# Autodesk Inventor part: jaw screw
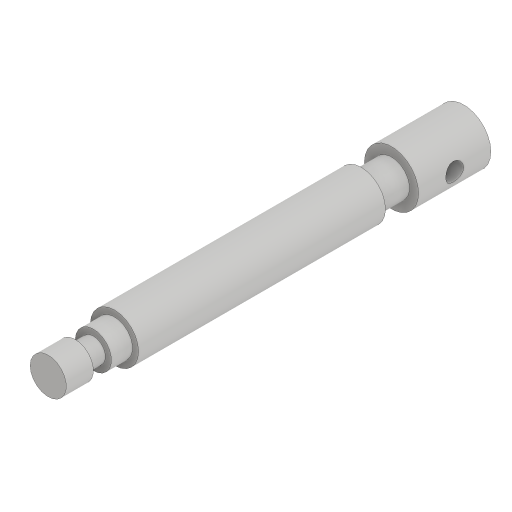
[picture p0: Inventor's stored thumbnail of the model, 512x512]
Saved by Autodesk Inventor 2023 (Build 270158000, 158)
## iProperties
Created: 2016-03
Part Number: jaw screw
Material: Generic
Document SubType Name: Modeling
Designer: Sandeep
Density: 1 g/cm^3
Appearance: Default
Mass: 25.5852 g
Surface Area: 75.8462 cm^2
Volume: 25.5852 cm^3
Author: Sandeep
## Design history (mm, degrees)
sketch "Sketch1"
  geometry: L1 (0, -138)-(-6, -138); L2 (-6, -116)-(-6, -116); L3 (-6, -116)-(-8, -116); L4 (-8, -116)-(-8, -34); L5 (-8, -34)-(-6, -34); L6 (-6, -34)-(-6, -24); L7 (-6, -24)-(-9, -24); L8 (-9, -24)-(-9, 0); L9 (-9, 0)-(0, 0); L10 (0, 0)-(0, -138); L11 (0, 0)-(0, 14.581); L12 (-6, -116)-(-6, -123); L13 (-6, -123)-(-4, -123); L14 (-4, -123)-(-4, -129); L15 (-4, -129)-(-6, -129); L16 (-6, -129)-(-6, -138); 1 other entity
  constraints: 32 end point, 10 perpendicular, 3 point on line, 3 vertical, 1 coincident, 1 horizontal, 2 other
  dimensions: "d0" = 18 diameter of L8 L11; "d1" = 12 diameter of L6 L11; "d3" = 24 distance of L7.end L8.end; "d4" = 10 distance of L5.end L6.end; "d5" = 82 distance of L3.end L4.end; "d6" = 138 distance between parallel lines of L1 L9; "d8" = 16 diameter of L4 L11; "d10" = 6 distance of L13.end L14.end; "d11" = 9 distance of L15.end L1.end; "d12" = 8 diameter of L14 L11
revolve "Revolution1" sketch "Sketch1" stored, may be unused: angle "d9" = 90 deg
sketch "Sketch2"
  geometry: L1 (0, -9)-(0, 9) reference; L2 (0, 0)-(-20.975, 0); C1 r 3 at (-12, 0)
  constraints: 2 end point, 1 centre point, 1 horizontal, 1 point on line
  dimensions: "d13" = 6 diameter of C1; "d14" = 12 distance from line of L1 C1.centre
extrude "Extrusion1" cut sketch "Sketch2" distance "d15" = 25; taper "d16" = 0 deg
body "Solid1"
